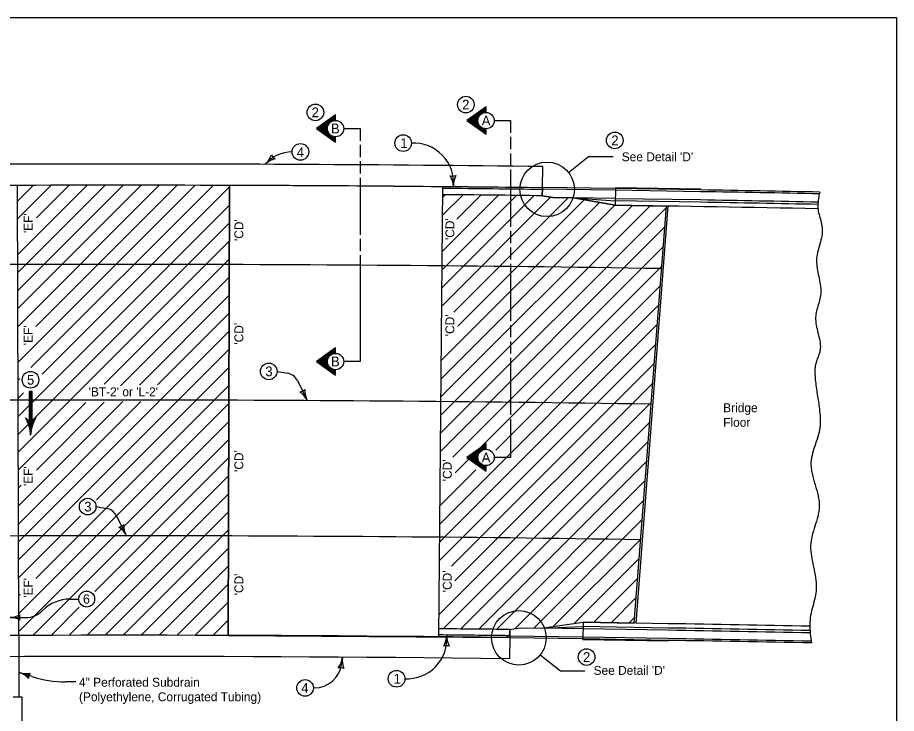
# Model space of a CAD drawing. Extents: x 10130 to 81668, y 5440 to 21644.
# Drawn here: x 22410 to 24068, y 8632 to 9944 of the extents above; entities that cross this region are included whole.
import ezdxf

# ---------------------------------------------------------------- set-up
doc = ezdxf.new("R2010")
doc.units = 0
for name, color, linetype in [('Default', 7, 'Continuous'), ('dsnstdblockInterim', 7, 'Continuous'), ('dsnStdBlockModified', 7, 'Continuous'), ('dsnStdBorder', 7, 'Continuous'), ('dsnstdModifiedBlock', 7, 'Continuous'), ('SheetBorder', 7, 'Continuous')]:
    doc.layers.add(name, color=color, linetype=linetype)

msp = doc.modelspace()

# ---------------------------------------------------------------- linework, layer by layer
at = {"layer": 'Default'}
for p, q in [((23399.9, 9623), (23400.4, 9663)), ((23338.2, 8774.3), (23337.8, 8735))]:
    msp.add_line(p, q, dxfattribs=at)
for radius, start in [(65123.7, 89.30428), (64195, 89.350122)]:
    msp.add_arc((22609.7, -55455.9), radius, start, 90.886963, dxfattribs=at)
msp.add_spline([(23923, 9614.9), (23920.9, 9605.3), (23920, 9598.3), (23919.4, 9591.4), (23920.2, 9579.1), (23923.2, 9566.8), (23926.4, 9554.5), (23927.7, 9542.2), (23926, 9528.2), (23922.4, 9514.1), (23918.8, 9500.2), (23916.9, 9486.1), (23918.1, 9471.1), (23921, 9456), (23924, 9440.9), (23925.1, 9425.8), (23923.4, 9414), (23920.2, 9402.3), (23916.9, 9390.6), (23915.1, 9378.9), (23916.3, 9364.2), (23919.6, 9349.4), (23922.9, 9334.5), (23923.9, 9319.9), (23922.2, 9311), (23919.1, 9302.3), (23915.9, 9293.6), (23914.2, 9284.7), (23913.9, 9271.1), (23914.9, 9257.5), (23918.8, 9230), (23922.7, 9202.5), (23923.9, 9182.1), (23923.6, 9175.3), (23920.5, 9157.5), (23914.9, 9140), (23909.4, 9122.4), (23906.4, 9104.7), (23906.8, 9094.3), (23908.4, 9083.9), (23914.1, 9063.1), (23919.8, 9042.3), (23922, 9021.6), (23921.1, 9012.3), (23919.2, 9003.1), (23913.7, 8984.8), (23908.4, 8966.4), (23905.8, 8948), (23907.3, 8928), (23911.2, 8908), (23915, 8887.9), (23916.4, 8867.9), (23914.1, 8850.8), (23909.8, 8833.7), (23905.8, 8816.5), (23904.2, 8799.3), (23904.5, 8790.6), (23905.1, 8781.9), (23907.1, 8764.6)], degree=3, dxfattribs=at)
at = {"layer": 'dsnstdblockInterim'}
for p, q in [((23399.9, 9623.8), (23399.7, 9608)), ((23537.7, 9621.6), (23399.9, 9623.8)), ((23537.7, 9618.3), (23399.9, 9620.5)), ((23537.7, 9623.2), (23537.2, 9590.1)), ((23698.2, 9620.7), (23537.7, 9623.2)), ((23698.2, 9619), (23537.7, 9621.6)), ((23698.1, 9615.7), (23537.7, 9618.3)), ((23698.2, 9620.7), (23698.2, 9619)), ((23399.7, 9608), (23419.3, 9604.5)), ((23419.3, 9604.5), (23458.7, 9603.8)), ((23537.4, 9602.6), (23458.7, 9603.8)), ((23458.7, 9603.8), (23537.2, 9590.1)), ((23458.7, 9603.8), (23537.3, 9598.3)), ((23697.8, 9595.7), (23537.3, 9598.3)), ((23697.9, 9600), (23537.4, 9602.5)), ((23633.9, 9588.6), (23537.2, 9590.1)), ((23576.5, 8802), (23637.2, 9588.5)), ((23397.6, 8792.4), (23476.5, 8803.6)), ((23476.5, 8803.6), (23476, 8770.5)), ((23576.5, 8802), (23476.5, 8803.6)), ((23637, 8801), (23576.5, 8802)), ((23338.5, 8790), (23338.2, 8774.3)), ((23338.5, 8790), (23358.2, 8793)), ((23358.2, 8793), (23397.6, 8792.4)), ((23397.6, 8792.4), (23476.4, 8795.4)), ((23476.3, 8791.1), (23397.6, 8792.4)), ((23636.8, 8788.5), (23476.3, 8791.1)), ((23636.8, 8792.8), (23476.4, 8795.4)), ((23476, 8772.1), (23338.2, 8774.3)), ((23476, 8775.4), (23338.3, 8777.6)), ((23636.5, 8772.8), (23476, 8775.4)), ((23636.5, 8769.5), (23476, 8772.1)), ((23636.4, 8767.9), (23476, 8770.5)), ((23636.5, 8769.5), (23636.4, 8767.9))]:
    msp.add_line(p, q, dxfattribs=at)
for radius, start, end in [(65080.7, 88.844392, 89.041687), (65084, 88.843728, 89.041689), (65065, 88.846272, 89.041677), (65052.5, 88.846229, 89.183021), (65060.7, 88.846493, 89.041674), (64265.1, 88.845683, 89.08406), (64256.9, 88.845199, 89.08406), (64252.6, 88.84489, 89.08406), (64236.9, 88.8431, 89.08406), (64233.6, 88.84258, 89.08406)]:
    msp.add_arc((22609.7, -55455.9), radius, start, end, dxfattribs=at)
at = {"layer": 'dsnStdBlockModified'}
for p, q in [((23449.1, 9652), (23487.1, 9682.2)), ((23487.1, 9682.2), (23533.1, 9682.2)), ((23056.1, 9495.7), (23056.1, 9295.4)), ((22899.5, 9276.8), (22919, 9273.5)), ((22937.8, 9259.5), (22956.4, 9221.7)), ((22558.1, 9021.8), (22577.6, 9018.5)), ((22596.4, 9004.6), (22615, 8966.7)), ((22509.2, 8847.4), (22525.5, 8847.4)), ((22394.6, 8812.8), (22425.9, 8812.8)), ((23021, 8724.8), (23022.7, 8737.9)), ((23395.9, 8742.4), (23433.9, 8712.2)), ((23433.9, 8712.2), (23479.9, 8712.2)), ((22520.1, 8691.3), (22500.5, 8691.3))]:
    msp.add_line(p, q, dxfattribs=at)
for points in [[(23309, 9749.7), (23339.9, 9749.7), (23339.9, 9726.6)], [(23025.2, 9734.7), (23056.1, 9734.7), (23056.1, 9711.5)], [(23339.9, 9718.9), (23339.9, 9695.8)], [(23056.1, 9703.8), (23056.1, 9680.7)], [(23339.9, 9688), (23339.9, 9664.9)], [(23056.1, 9673), (23056.1, 9649.9)], [(23339.9, 9657.2), (23339.9, 9549.3)], [(23056.1, 9642.1), (23056.1, 9534.2)], [(23339.9, 9541.6), (23339.9, 9518.4)], [(23056.1, 9526.5), (23056.1, 9503.4)], [(23339.9, 9510.7), (23339.9, 9487.6)], [(23339.9, 9479.9), (23339.9, 9372)], [(23339.9, 9364.2), (23339.9, 9341.1)], [(23339.9, 9333.4), (23339.9, 9310.3)], [(23056.1, 9306.9), (23056.1, 9295.4), (23025.2, 9295.4)], [(23339.9, 9302.6), (23339.9, 9194.6)], [(23339.9, 9186.9), (23339.9, 9163.8)], [(23339.9, 9166.4), (23339.9, 9114.4), (23309, 9114.4)]]:
    msp.add_lwpolyline(points, dxfattribs=at)
for centre, radius, start, end in [((23157.1, 9632.2), 75.2, 354.4077, 93.0768), ((22927.7, 9623.9), 66.8, 90, 139.4393), ((22914.7, 9248.2), 25.7, 26.2458, 80.4677), ((22573.3, 8993.2), 25.7, 26.2458, 80.4677), ((22509.2, 8774), 73.4, 90, 135), ((22425.9, 8856.8), 44.1, 270, 315), ((23144.6, 8772.3), 75.2, 266.9232, 5.5923), ((22970, 8731.2), 51.4, 270, 352.7713), ((22500.5, 8896.9), 205.6, 252.1406, 270)]:
    msp.add_arc(centre, radius, start, end, dxfattribs=at)
at = {"layer": 'dsnStdBorder'}
for p, q in [((22410.3, 9598.6), (22439.3, 9627.6)), ((22410.4, 9564.8), (22473.3, 9627.7)), ((22410.6, 9497.1), (22541.3, 9627.8)), ((22410.7, 9463.2), (22575.3, 9627.8)), ((22410.8, 9429.4), (22609.2, 9627.8)), ((22410.9, 9395.6), (22643.2, 9627.8)), ((22411, 9361.7), (22677.1, 9627.8)), ((22411.2, 9294.1), (22744.9, 9627.7)), ((22435.1, 9284), (22778.7, 9627.6)), ((22444.6, 9361.3), (22711, 9627.7)), ((22445.9, 9566.3), (22507.3, 9627.7)), ((22456.4, 9271.4), (22809.6, 9624.6)), ((23210.1, 9399.8), (23415.4, 9605.2)), ((23210.4, 9434.1), (23384.5, 9608.2)), ((23210.7, 9468.4), (23350.9, 9608.6)), ((23211, 9502.6), (23317.4, 9609)), ((23211.7, 9571.1), (23250.2, 9609.7)), ((23212, 9605.4), (23216.6, 9610)), ((23232.6, 9388.5), (23448.2, 9604)), ((23238.4, 9563.9), (23283.8, 9609.3)), ((23240.4, 9362.3), (23478.5, 9600.4)), ((22411.6, 9192.6), (22809.5, 9590.5)), ((23207.8, 9160), (23633.7, 9585.9)), ((23208.2, 9194.3), (23602.9, 9589)), ((23208.5, 9228.6), (23569.5, 9589.6)), ((23208.8, 9262.8), (23536.3, 9590.3)), ((23209.1, 9297.1), (23507.4, 9595.3)), ((22411.7, 9158.7), (22809.4, 9556.5)), ((23207.5, 9125.8), (23630.8, 9549.1)), ((22411.8, 9124.9), (22809.3, 9522.4)), ((23230.9, 9115.2), (23628, 9512.3)), ((22573.6, 9252.7), (22809.2, 9488.4)), ((23235.3, 9085.6), (23625.1, 9475.5)), ((22604.5, 9249.7), (22809.1, 9454.4)), ((23311.9, 9128.3), (23622.3, 9438.7)), ((22639.8, 9251.1), (22809, 9420.3)), ((23206.3, 8988.7), (23619.5, 9402)), ((22674.1, 9251.5), (22808.9, 9386.3)), ((23205.9, 8954.5), (23616.6, 9365.2)), ((22412.3, 8955.7), (22808.8, 9352.2)), ((22412.4, 8921.9), (22808.7, 9318.2)), ((23205.6, 8920.2), (23613.8, 9328.4)), ((22559.2, 9034.7), (22808.6, 9284.1)), ((23228.7, 8909.4), (23610.9, 9291.6)), ((22411.4, 9260.2), (22414.2, 9263.1)), ((22444.3, 8885.9), (22808.5, 9250.1)), ((23235, 8881.7), (23608.1, 9254.8)), ((22411.5, 9226.4), (22421.5, 9236.4)), ((22434.8, 9184.1), (22434.8, 9238.6)), ((22411.9, 9091), (22539, 9218.2)), ((22412.1, 9023.4), (22608.5, 9219.7)), ((22412.2, 8989.5), (22642.6, 9219.9)), ((22412.7, 8820.4), (22808.4, 9216)), ((22445.5, 9090.7), (22573.4, 9218.6)), ((23204.7, 8817.5), (23605.3, 9218)), ((22431.7, 9184.2), (22431.7, 9184.2)), ((22438.1, 9184.3), (22438.1, 9184.3)), ((22412.8, 8786.5), (22808.3, 9182)), ((23212.5, 8791.3), (23602.4, 9181.3)), ((22439.2, 8778.9), (22808.2, 9147.9)), ((23246.1, 8791), (23599.6, 9144.5)), ((22555.9, 8861.7), (22808.1, 9113.9)), ((23279.7, 8790.7), (23596.8, 9107.7)), ((23206.6, 9023), (23274.5, 9091)), ((22507.2, 8779.1), (22808, 9079.8)), ((23313.3, 8790.3), (23593.9, 9070.9)), ((22412, 9057.2), (22416.7, 9061.9)), ((22541.2, 8779.1), (22807.9, 9045.8)), ((23348.5, 8791.6), (23591.1, 9034.1)), ((22412.5, 8888), (22528.7, 9004.2)), ((22575.2, 8779.2), (22807.8, 9011.8)), ((23383.5, 8792.6), (23588.2, 8997.4)), ((22609.1, 8779.2), (22807.7, 8977.7)), ((23420.4, 8795.6), (23585.4, 8960.6)), ((22643, 8779.2), (22807.6, 8943.7)), ((23460, 8801.2), (23582.6, 8923.8)), ((22677, 8779.1), (22807.4, 8909.6)), ((23496, 8803.3), (23579.7, 8887)), ((22710.9, 8779.1), (22807.3, 8875.6)), ((22412.6, 8854.2), (22414.9, 8856.5)), ((22744.7, 8779), (22807.2, 8841.5)), ((23529.4, 8802.7), (23576.9, 8850.2)), ((22473.2, 8779), (22526.1, 8831.9)), ((22778.6, 8778.9), (22807.1, 8807.5)), ((23562.8, 8802.2), (23574, 8813.5)), ((22412.8, 8778.8), (22412.8, 8663.1)), ((23332.2, 8775.3), (23338.3, 8781.4)), ((22437.4, 8701.2), (22412.8, 8709.1)), ((22412.8, 8709.1), (22431.7, 8703.1)), ((22401.5, 8663.1), (22418, 8663.1)), ((22418, 8663.1), (22418, 8590.7))]:
    msp.add_line(p, q, dxfattribs=at)
for points in [[(23293.6, 9765.1), (23293.6, 9775.4), (23257.6, 9749.7), (23293.6, 9724), (23293.6, 9734.3)], [(23292.6, 9733.3), (23292.7, 9725.9), (23259.6, 9749.7), (23292.8, 9773.8), (23292.5, 9765.9), (23291.1, 9765.5), (23291.7, 9771.2), (23261.7, 9749.7), (23291.7, 9727.9), (23291.4, 9733.5), (23290.3, 9733.7), (23290.4, 9730), (23263.8, 9749.8), (23290.4, 9768.6), (23289.9, 9765.4), (23288.7, 9765.1), (23288.9, 9766.2), (23266, 9749.5), (23289.3, 9732), (23288.1, 9733.9), (23268, 9749.4), (23280.4, 9759.1), (23279.6, 9757.3), (23270.1, 9749.3), (23279.3, 9742.3), (23278.4, 9744.2), (23272.1, 9749), (23278.4, 9754.5), (23277.8, 9752.1), (23273.7, 9749), (23277.9, 9745.7), (23277.6, 9747.4), (23275.2, 9748.9), (23277.6, 9750.3), (23277.4, 9748.8), (23276.6, 9748.9)], [(23009.8, 9750.1), (23009.8, 9760.4), (22973.8, 9734.7), (23009.8, 9709), (23009.8, 9719.2)], [(23008.8, 9718.2), (23008.9, 9710.8), (22975.8, 9734.7), (23009, 9758.7), (23008.7, 9750.8), (23007.3, 9750.4), (23007.9, 9756.1), (22978, 9734.7), (23007.9, 9712.9), (23007.6, 9718.4), (23006.5, 9718.6), (23006.6, 9715), (22980, 9734.7), (23006.6, 9753.5), (23006.1, 9750.3), (23004.9, 9750), (23005.1, 9751.1), (22982.2, 9734.4), (23005.5, 9716.9), (23004.3, 9718.8), (22984.2, 9734.3), (22996.6, 9744.1), (22995.8, 9742.3), (22986.3, 9734.2), (22995.5, 9727.2), (22994.6, 9729.1), (22988.3, 9734), (22994.6, 9739.5), (22994, 9737.1), (22989.9, 9733.9), (22994.1, 9730.6), (22993.9, 9732.3), (22991.4, 9733.8), (22993.8, 9735.2), (22993.6, 9733.7), (22992.8, 9733.8)], [(23009.8, 9310.9), (23009.8, 9321.1), (22973.8, 9295.4), (23009.8, 9269.7), (23009.8, 9280)], [(23008.8, 9279), (23008.9, 9271.6), (22975.8, 9295.4), (23009, 9319.5), (23008.7, 9311.6), (23007.3, 9311.2), (23007.9, 9316.9), (22978, 9295.4), (23007.9, 9273.7), (23007.6, 9279.2), (23006.5, 9279.4), (23006.6, 9275.8), (22980, 9295.5), (23006.6, 9314.3), (23006.1, 9311.1), (23004.9, 9310.8), (23005.1, 9311.9), (22982.2, 9295.2), (23005.5, 9277.7), (23004.3, 9279.6), (22984.2, 9295.1), (22996.6, 9304.8), (22995.8, 9303), (22986.3, 9295), (22995.5, 9288), (22994.6, 9289.9), (22988.3, 9294.7), (22994.6, 9300.3), (22994, 9297.9), (22989.9, 9294.7), (22994.1, 9291.4), (22993.9, 9293.1), (22991.4, 9294.6), (22993.8, 9296), (22993.6, 9294.5), (22992.8, 9294.6)], [(22437.8, 9184.2), (22437.8, 9238.6), (22431.7, 9238.6), (22431.7, 9184.2), (22437, 9184.4), (22437.2, 9237.9), (22432.3, 9237.8), (22432.5, 9185.4), (22436.1, 9185.3), (22436.3, 9237.2), (22433.1, 9237), (22433.1, 9186.1), (22435.4, 9185.9), (22435.7, 9236.6), (22433.8, 9236.5), (22433.9, 9186.8)], [(22441.9, 9185.7), (22438.2, 9183.4), (22432.8, 9183.1), (22428.1, 9185.1), (22431.4, 9177), (22434.2, 9167.6), (22434.8, 9165), (22436.1, 9171.8), (22439.5, 9181.6), (22441.1, 9184.6), (22429.7, 9183.5), (22434.6, 9169), (22438.9, 9183.1), (22431, 9182.6), (22434.6, 9172.7), (22436.9, 9181.8), (22432.3, 9182.2), (22434.4, 9175.9), (22435.7, 9180.7), (22433.6, 9181), (22434.2, 9178.6)], [(23293.6, 9129.8), (23293.6, 9140.1), (23257.6, 9114.4), (23293.6, 9088.7), (23293.6, 9099)], [(23292.6, 9098), (23292.7, 9090.5), (23259.6, 9114.4), (23292.8, 9138.4), (23292.5, 9130.5), (23291.1, 9130.2), (23291.7, 9135.9), (23261.7, 9114.4), (23291.7, 9092.6), (23291.4, 9098.1), (23290.3, 9098.4), (23290.4, 9094.7), (23263.8, 9114.5), (23290.4, 9133.3), (23289.9, 9130.1), (23288.7, 9129.8), (23288.9, 9130.9), (23266, 9114.2), (23289.3, 9096.6), (23288.1, 9098.6), (23268, 9114), (23280.4, 9123.8), (23279.6, 9122), (23270.1, 9113.9), (23279.3, 9107), (23278.4, 9108.8), (23272.1, 9113.7), (23278.4, 9119.2), (23277.8, 9116.8), (23273.7, 9113.6), (23277.9, 9110.4), (23277.6, 9112.1), (23275.2, 9113.6), (23277.6, 9115), (23277.4, 9113.5), (23276.6, 9113.6)], [(22432.4, 8706.7), (22430.6, 8703.4), (22430.2, 8699.6), (22426.6, 8703), (22420.4, 8706.7), (22428.1, 8706), (22431.7, 8706.4), (22429.9, 8703.6), (22429.5, 8701.2), (22427.1, 8703.5), (22423.7, 8705.6), (22428, 8705.5), (22430.3, 8705.5), (22429, 8702.6), (22426.6, 8704.7), (22429, 8704.7), (22428.7, 8703.6), (22427.8, 8704.3)]]:
    msp.add_lwpolyline(points, dxfattribs=at)
msp.add_lwpolyline([(23633.9, 9588.6), (23537.2, 9590.1), (23458.7, 9603.8), (23419.3, 9604.5), (23399.7, 9608), (23399.9, 9623), (23050.2, 9626.3), (22809.7, 9627.5), (22807, 8778.9), (23338.2, 8775), (23338.2, 8775), (23338.5, 8790), (23358.2, 8793), (23397.6, 8792.4), (23476.5, 8803.6), (23573.2, 8802)], close=True, dxfattribs=at)
for centre, radius in [((23255.5, 9779.9), 15.7), ((22971.7, 9765.3), 15.7), ((23293.6, 9749.7), 15.4), ((23009.8, 9734.7), 15.4), ((23137.3, 9707.3), 15.7), ((23536.4, 9712.4), 15.7), ((22943.5, 9690.7), 15.7), ((23408.8, 9620.1), 51.4), ((23009.8, 9295.4), 15.4), ((22883.7, 9276.8), 15.7), ((22434.5, 9260.9), 15.7), ((23293.6, 9114.4), 15.4), ((22542.3, 9021.8), 15.7), ((22540.5, 8847.4), 15), ((23355.6, 8774.3), 51.4), ((23483.2, 8738.1), 15.7), ((23124.8, 8697.1), 15.7), ((22952.2, 8679.8), 15.7)]:
    msp.add_circle(centre, radius, dxfattribs=at)
for centre, radius, start, end in [((22846.8, 9699.9), 44.4, 312.7719, 340.8444), ((22904.3, 9692.6), 17.1, 205.0386, 240.5053), ((22907.1, 9634.7), 44.4, 104.6994, 132.7719), ((23230.9, 9662.1), 17.1, 253.8465, 289.3132), ((23187.6, 9623.6), 44.4, 1.5799, 29.6523), ((23276.3, 9626.1), 44.4, 153.5074, 181.5799), ((22609.7, -55455.9), 64934.4, 89.104273, 90.886963), ((22940, 9255.1), 17.1, 278.5122, 313.9789), ((22916.6, 9202), 44.4, 26.2455, 54.318), ((22996.2, 9241.3), 44.4, 178.1731, 206.2455), ((22434.8, 9195.4), 11.6, 211.7147, 328.2853), ((22368.5, 9154.4), 66.3, 1.6842, 31.7143), ((22501, 9154.4), 66.3, 148.2857, 178.3158), ((22598.6, 9000.1), 17.1, 278.5122, 313.9789), ((22654.8, 8986.3), 44.4, 178.1731, 206.2455), ((22609.7, -55455.9), 64422.6, 89.132259, 90.886963), ((22575.2, 8947.1), 44.4, 26.2455, 54.318), ((22394.6, 8855.1), 42.3, 270, 298.0725), ((22430.1, 8812.8), 16.3, 162.2666, 197.7334), ((22394.6, 8770.5), 42.3, 61.9275, 90), ((23175.1, 8780.8), 44.4, 330.3477, 358.4201), ((23263.8, 8778.4), 44.4, 178.4201, 206.4926), ((23218.4, 8742.4), 17.1, 70.6868, 106.1535), ((22978.7, 8743.4), 44.4, 324.6988, 352.7713), ((23066.7, 8732.3), 44.4, 172.7713, 200.8438), ((23018, 8700.9), 17.1, 65.0379, 100.5046), ((22399.5, 8667.5), 43.7, 44.0691, 72.1415), ((22426.2, 8750.7), 43.7, 252.1415, 280.214), ((22447.7, 8697.9), 16.9, 144.4082, 179.8749)]:
    msp.add_arc(centre, radius, start, end, dxfattribs=at)
at = {"layer": 'dsnstdModifiedBlock'}
for p, q in [((22412.8, 8778.9), (22410.2, 9627.5)), ((22807, 8778.9), (22809.7, 9627.5)), ((23204.3, 8776.4), (23212.2, 9625)), ((23573.2, 8802), (23633.9, 9588.6))]:
    msp.add_line(p, q, dxfattribs=at)
for points in [[(23399.9, 9623), (23399.7, 9608), (23419.3, 9604.5), (23458.7, 9603.8), (23537.2, 9590.1), (23633.9, 9588.6)], [(23338.2, 8775), (23338.5, 8790), (23358.2, 8793), (23397.6, 8792.4), (23476.5, 8803.6), (23476.5, 8803.6), (23573.2, 8802)]]:
    msp.add_lwpolyline(points, dxfattribs=at)
for radius, start, end in [(65083.7, 89.30428, 90.886963), (65080.4, 89.30428, 89.469594), (65068.7, 89.304331, 89.469594), (64678.5, 89.11821, 90.886963), (64250, 89.35006, 89.469594), (64235, 89.350122, 90.886963), (64238.4, 89.350122, 89.469594)]:
    msp.add_arc((22609.7, -55455.9), radius, start, end, dxfattribs=at)
at = {"layer": 'SheetBorder'}
msp.add_lwpolyline([(20932.5, 9944), (24067.5, 9944), (24067.5, 7924), (20932.5, 7924)], close=True, dxfattribs=at)

# ---------------------------------------------------------------- texts
at = {"layer": 'dsnStdBlockModified'}
for s, height, p in [('2', 18.4, (23248.6, 9770.7)), ('2', 18.4, (22964.7, 9756.1)), ('A', 18.4, (23285.4, 9740.5)), ('B', 18.4, (23001.2, 9725.5)), ('1', 18.4, (23131.9, 9698.1)), ('2', 18.4, (23529.8, 9703.2)), ('4', 18.4, (22936.7, 9680.8)), ("See Detail 'D'", 16.8, (23549.6, 9673.1)), ('B', 18.4, (23001.2, 9286.3)), ('3', 18.4, (22877.3, 9267.6)), ('5', 18.4, (22427.9, 9251.7)), ("'BT-2' or 'L-2'", 16.8, (22544.2, 9229.9)), ('Bridge', 16.8, (23740.8, 9199.8)), ('Floor', 16.8, (23740.8, 9172.3)), ('A', 18.4, (23285.4, 9105.2)), ('3', 18.4, (22535.9, 9012.6)), ('6', 17.5, (22533.5, 8838.7)), ('2', 18.4, (23476.6, 8728.9)), ("See Detail 'D'", 16.8, (23496.4, 8704.5)), ('1', 18.4, (23119.4, 8688)), ('4" Perforated Subdrain ', 16.8, (22526, 8682.1)), ('4', 18.4, (22945.1, 8670.6)), ('(Polyethylene, Corrugated Tubing)', 16.8, (22526, 8654.7))]:
    msp.add_text(s, height=height, dxfattribs=at).set_placement(p)
for s, p in [("'EF'", (22438.4, 9537.6)), ("'CD'", (23233.9, 9524.5)), ("'CD'", (22835.9, 9522.7)), ("'CD'", (23233.9, 9343.1)), ("'CD'", (22835.9, 9327.3)), ("'EF'", (22438.4, 9326.2)), ("'CD'", (22835.9, 9087.1)), ("'CD'", (23228.9, 9069.6)), ("'EF'", (22438.4, 9060.5)), ("'EF'", (22438.4, 8849.9)), ("'CD'", (22835.9, 8854.5)), ("'CD'", (23228.9, 8860.3))]:
    msp.add_text(s, height=16.8, rotation=90, dxfattribs=at).set_placement(p)

doc.saveas('drawing.dxf')
